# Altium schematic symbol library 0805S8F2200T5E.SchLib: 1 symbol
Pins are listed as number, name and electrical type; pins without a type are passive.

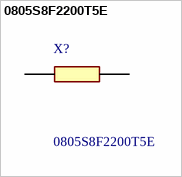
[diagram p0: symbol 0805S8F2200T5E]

## 0805S8F2200T5E
designator X?
Manufacturer_Name: ROYALOHM; Geometry.Height: 0.65mm
footprint RESC2013X65N
pins: 1, 2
